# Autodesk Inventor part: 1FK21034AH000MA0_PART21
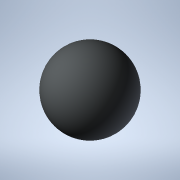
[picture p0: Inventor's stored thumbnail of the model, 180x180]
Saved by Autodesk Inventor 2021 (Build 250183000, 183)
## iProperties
Created: 2025-04
Part Number: 1FK21034AH000MA0_PART21
Material: Generic
Catalog Web Link: www.3dfindit.com
Description: -Servo synchronous motor
Document SubType Name: Modeling
Designer: psAdmin
Mass: 0.113097 g
Surface Area: 1.13097 cm^2
Volume: 0.113097 cm^3
Density: 1 g/cm^3
Appearance: PSOLRGB-212-217-219
Category: PARTsolutions
Title: 1FK21034AH000MA0_PART21
Author: Cadenas PARTsolutions
Comments: Servo synchronous motor
Sending System: PARTsolutions
Preprocessor: ST-DEVELOPER v19.3
PSOL_IDENT_0: {$CADENAS_DATA/23d-libs/siemens_ag/_cat_/ec/b7/1fk21034ah000ma0.prj},216 {VTYP=3D},{NB=1FK21034AH000
PSOL_IDENT_1: MA0_PART21},{LINA=1FK21034AH000MA0_PART21},{NN=1FK21034AH000MA0_PART21},{NOPRJ=TRUE},{DATE=19.08.202
PSOL_IDENT_2: 5 14:01:05},{GEOMDATE=30.07.2025 02:01:02},{VERSION=},{LINEID=10},{WBVAR=},{WBNUMERIC=}  {NB=1FK2103
PSOL_IDENT_3: 4AH000MA0_PART21},{LINA=1FK21034AH000MA0_PART21},{KT=DUMMY},{PREVIEW=../../../_pool_/7c/50/p_d211_xx
PSOL_IDENT_4: _00932j.png},{DESCSHORT=SIMOTICS S-1FK2 HD, SINAMICS S210 3AC 400V-480V, 1.01 Nm, 4500 rpm},{DESCLON
PSOL_IDENT_5: G=SIMOTICS S-1FK2 HD servo motor M0=1.27 Nm; PN = 0.48 kW at nN=4500 rpm (380-480 V); PN = 0.3 kW at
PSOL_IDENT_6: nN=2500 rpm (200-240 V); degree of protection IP64; cylindrical shaft D14 x 30 mm; absolute encoder
PSOL_IDENT_7: 22-bit + 12-bit multiturn (encoder AM22DQC); with OCC interface; plug size M17, rotatable; SIMOTICS
PSOL_IDENT_8: S-1FK2 servomotorfor a wide range of uses in industrial environments. SIMOTICS S‑1FK2 servomotors a
PSOL_IDENT_9: re compact synchronous motors with a high dynamic performance that set themselves apart as a result
PSOL_IDENT_10: of their high power density, degree of protection and overload capability. The motors are available
PSOL_IDENT_11: in two variants: as High Dynamic variant (highest dynamic performance as a result of the low intrins
PSOL_IDENT_12: ic moment of inertia for applications demanding a high dynamic performance with low moved masses) -
PSOL_IDENT_13: and as Compact variant (precise and stable closed-loop control for medium up to large moved masses a
PSOL_IDENT_14: s a result of a medium intrinsic moment of inertia). SIMOTICSS‑1FK2 servomotors fully exploit their
PSOL_IDENT_15: strengths in a system with the SINAMICSS210 frequency converter and simple connection using the one
PSOL_IDENT_16: cable connection (OCC). Advantages include the short control and positioning times, fast and precise
PSOL_IDENT_17: correction of disturbing quantities as well as stable control with a high dynamic performance. The
PSOL_IDENT_18: servo motors can be configured to address a wide range of requirements. For example with and without
PSOL_IDENT_19: holding brake, IP64 or IP65 degree of protection, singleturn or multiturn absolute encoders - to na
PSOL_IDENT_20: me just a few. Further, the servomotors are available in different shaft heights extending from 20 t
PSOL_IDENT_21: o 100. A shaft sealing ring is available to achieve an IP65 degree of protection and for subsequent
PSOL_IDENT_22: mounting at the motor or as spare part. SIMOTICS - the optimum motor for each and every motion contr
PSOL_IDENT_23: ol application.},{INTNO=4034106444822},{SUPPLIERALTNO=1FK2103-4AH00-0MA0},{MANUID=1FK21034AH000MA0},
PSOL_IDENT_24: {MANUNAME=Siemens},{MANUTYPEDESC=SYNCHRONOUS MOTOR 1FK2 HD 1,27 NM},{AAU732=SIMOTICS},{AAO057=S-1FK2
PSOL_IDENT_25: },{AAU734=SIMOTICS S-1FK2 HD servo motor M0=1.27 Nm; PN = 0.48 kW at nN=4500 rpm (380-480 V); PN = 0
PSOL_IDENT_26: .3 kW at nN=2500 rpm (200-240 V); degree of protection IP64; cylindrical shaft D14 x 30 mm; absolute
PSOL_IDENT_27: encoder 22-bit + 12-bit multiturn (encoder AM22DQC); with OCC interface; plug size M17, rotatable;}
PSOL_IDENT_28: ,{AAW338=SYNCHRONOUS MOTOR 1FK2 HD 1,27 NM},{AAO742=SIMOTICS},{AAO663=4034106444822},{NOCUPEROU=1},{
PSOL_IDENT_29: PRICEQUANTITY=1},{QUANTITYMIN=1},{QUANTITYINT=1},{CTN=85015100},{COO=RO},{AAO676=1FK2103-4AH00-0MA0}
PSOL_IDENT_30: ,{AAO677=Siemens AG},{ORDERUNIT=C62},{CONTENTUNIT=C62}
NB: 1FK21034AH000MA0_PART21
NT: Servo synchronous motor
NBSYN: $MANUID._PART21
LINA: 1FK21034AH000MA0_PART21
CATALOG: SIEMENS
PREVIEW: ../../../_pool_/7c/50/p_d211_xx_00932j.png
DESCSHORT: SIMOTICS S-1FK2 HD, SINAMICS S210 3AC 400V-480V, 1.01 Nm, 4500 rpm
DESCLONG: SIMOTICS S-1FK2 HD servo motor M0=1.27 Nm; PN = 0.48 kW at nN=4500 rpm (380-480 V); PN = 0.3 kW at nN=2500 rpm (200-240 V); degree of protection IP64; cylindric
INTNO: 4034106444822
SUPPLIERALTNO: 1FK2103-4AH00-0MA0
MANUID: 1FK21034AH000MA0
MANUNAME: Siemens
MANUTYPEDESC: SYNCHRONOUS MOTOR 1FK2 HD 1,27 NM
AAU732: SIMOTICS
AAO057: S-1FK2
AAU734: SIMOTICS S-1FK2 HD servo motor M0=1.27 Nm; PN = 0.48 kW at nN=4500 rpm (380-480 V); PN = 0.3 kW at nN=2500 rpm (200-240 V); degree of protection IP64; cylindric
AAW338: SYNCHRONOUS MOTOR 1FK2 HD 1,27 NM
AAO742: SIMOTICS
AAO663: 4034106444822.0
NOCUPEROU: 1
PRICEQUANTITY: 1
QUANTITYMIN: 1
QUANTITYINT: 1
CTN: 85015100
COO: RO
ARTICLENO: 1FK21034AH000MA0_PART21
BOMINFO: 1FK21034AH000MA0_PART21
CREATOR: CADENAS GmbH
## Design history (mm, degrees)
feature "2025_04_17_15_01_37_0314"
body "Solid1"
